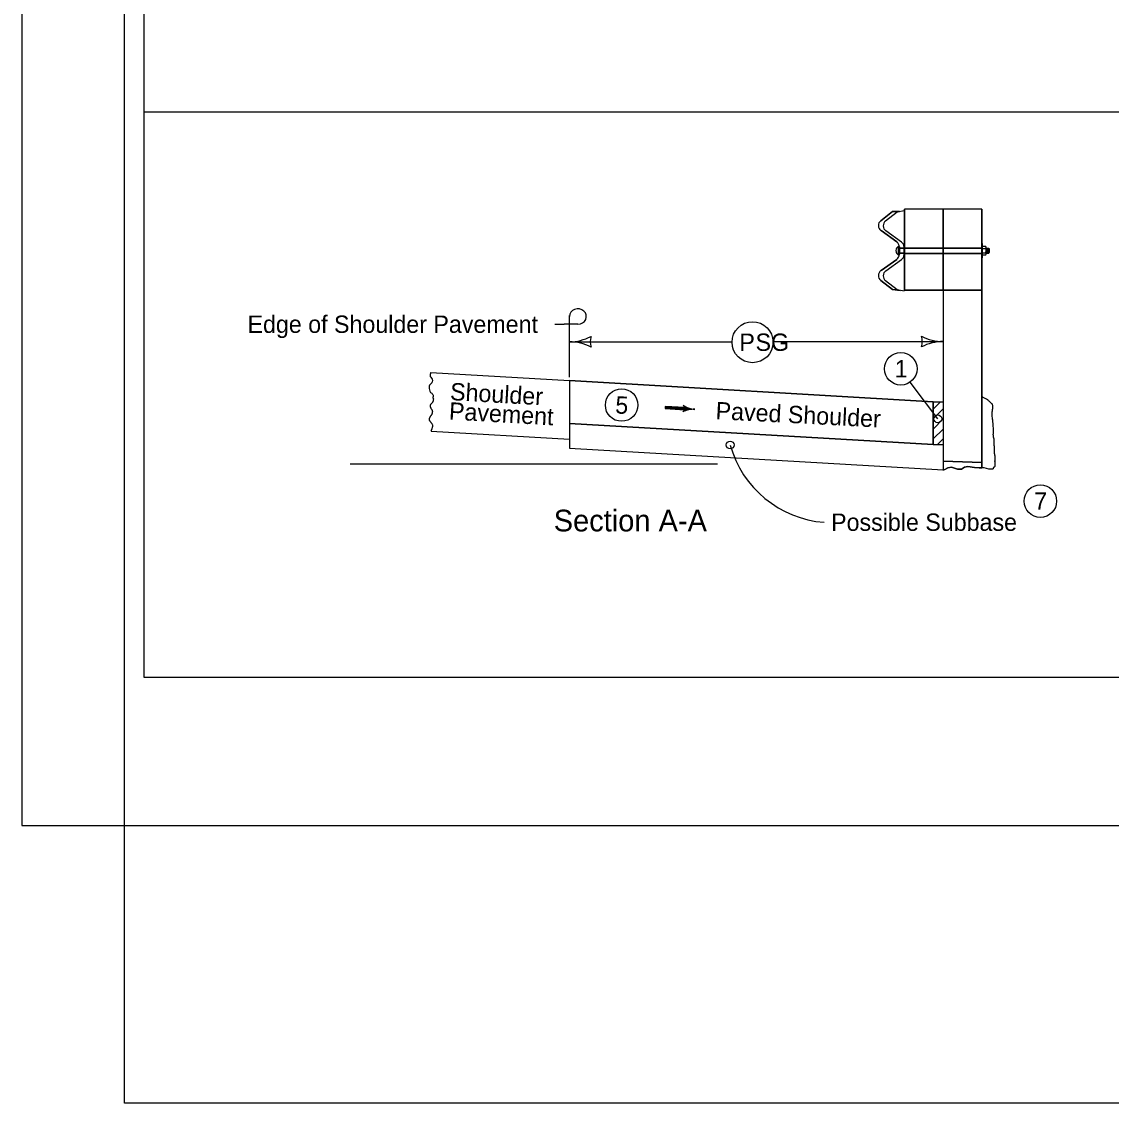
# Model space of a CAD drawing. Extents: x 10038 to 81668, y 7924 to 11018.
# Drawn here: x 10038 to 11041, y 7924 to 8921 of the extents above; entities that cross this region are included whole.
import ezdxf

# ---------------------------------------------------------------- set-up
doc = ezdxf.new("R2010")
doc.units = 0
for name, color, linetype in [('dsnCellElements', 7, 'Continuous'), ('DsnShtMinorGrid05', 7, 'Continuous'), ('DsnShtMinorGrid06', 7, 'Continuous'), ('DsnShtMinorGrid07', 7, 'Continuous'), ('DsnShtMinorGrid09', 7, 'Continuous'), ('DsnShtMinorGrid10', 7, 'Continuous'), ('DsnShtMinorGrid11', 7, 'Continuous'), ('DsnShtMinorGrid14', 7, 'Continuous'), ('Level 60', 7, 'Continuous'), ('SheetBorder', 7, 'Continuous')]:
    doc.layers.add(name, color=color, linetype=linetype)

msp = doc.modelspace()

# ---------------------------------------------------------------- linework, layer by layer
at = {"layer": 'dsnCellElements'}
msp.add_lwpolyline([(10037.7, 8180), (13358.6, 8180), (13358.6, 10373.4), (10037.7, 10373.4)], close=True, dxfattribs=at)
at = {"layer": 'DsnShtMinorGrid05'}
for p, q in [((10542.3, 8625.9), (10692.1, 8625.9)), ((10729.9, 8626.1), (10886.7, 8626.1))]:
    msp.add_line(p, q, dxfattribs=at)
msp.add_circle((10711, 8625.5), 18.9, dxfattribs=at)
for centre, radius, start, end in [((10542.3, 8668.4), 42.5, 270, 298.0725), ((10542.3, 8583.4), 42.5, 61.9275, 90), ((10577.9, 8625.9), 16.4, 162.2666, 197.7334), ((10851, 8626.1), 16.4, 342.2666, 17.7333), ((10886.7, 8668.6), 42.5, 241.9275, 270), ((10886.7, 8583.6), 42.5, 90, 118.0725), ((10784.6, 8557), 97.8, 195.5978, 265.558)]:
    msp.add_arc(centre, radius, start, end, dxfattribs=at)
at = {"layer": 'DsnShtMinorGrid06'}
for p, q in [((10150.3, 9926.7), (10150.3, 8316.7)), ((10150.3, 8316.7), (13246, 8316.7))]:
    msp.add_line(p, q, dxfattribs=at)
at = {"layer": 'DsnShtMinorGrid07'}
for p, q in [((10829.4, 8728.4), (10843.9, 8718)), ((10843.9, 8701.9), (10829.4, 8691.5))]:
    msp.add_line(p, q, dxfattribs=at)
for points in [[(10833.6, 8737.3), (10833.6, 8737.3), (10844.4, 8745.7), (10846.3, 8746), (10839.9, 8745.9), (10829.2, 8737.5)], [(10886.7, 8712.6), (10886.7, 8748.3), (10851.1, 8748.3), (10851.1, 8712.6), (10851.1, 8712.6), (10886.7, 8712.6)], [(10922.2, 8712.6), (10922.2, 8716.6), (10922.2, 8748.3), (10886.7, 8748.3), (10886.7, 8712.6), (10922.2, 8712.6)], [(10848.3, 8717.8), (10848.3, 8717.8), (10833.8, 8728.2), (10833.8, 8728.2)], [(10846.3, 8713.4), (10846.3, 8712.3), (10850.7, 8712.3), (10850.7, 8713.2), (10850.7, 8713.2)], [(10850.7, 8706.3), (10850.7, 8706.3), (10850.7, 8707.6), (10846.3, 8707.6), (10846.3, 8706.6), (10846.3, 8707.6), (10846.3, 8707.6), (10846.3, 8706.6)], [(10851.1, 8712.3), (10851.1, 8707.6), (10851.1, 8707.6), (10886.7, 8707.6), (10886.7, 8712.3), (10851.1, 8712.3), (10851.1, 8712.3)], [(10851.1, 8707.3), (10851.1, 8673.6), (10886.7, 8673.6), (10886.7, 8707.3), (10851.1, 8707.3)], [(10922.2, 8707.6), (10922.2, 8712.3), (10886.7, 8712.3), (10886.7, 8707.6), (10922.2, 8707.6)], [(10922.2, 8673.6), (10922.2, 8703.3), (10922.2, 8707.3), (10886.7, 8707.3), (10886.7, 8673.6), (10922.2, 8673.6)], [(10833.8, 8691.3), (10833.8, 8691.3), (10848.3, 8701.7), (10848.3, 8701.7)], [(10829.2, 8682.4), (10839.9, 8674), (10847, 8673.3), (10844.4, 8673.8), (10833.6, 8682.2), (10833.6, 8682.2)], [(10922.2, 8514.7), (10922.2, 8673.6), (10886.7, 8673.6), (10886.7, 8570.7), (10886.7, 8564), (10886.7, 8564), (10886.7, 8564), (10886.7, 8554.8), (10886.7, 8554.8), (10886.7, 8554.8), (10886.7, 8545.6), (10886.7, 8545.6), (10886.7, 8545.6), (10886.7, 8538.7), (10886.7, 8515.9), (10922.2, 8514.7)], [(10922.2, 8514.7), (10886.7, 8515.9), (10886.7, 8507.8), (10888.3, 8508.1), (10891, 8509.7), (10894.3, 8510.2), (10899.9, 8508.6), (10903.7, 8508.4), (10906.3, 8510.2), (10909.4, 8510.8), (10915.6, 8510.1), (10919.9, 8509.7), (10922.2, 8509.7), (10922.2, 8514.7)]]:
    msp.add_lwpolyline(points, dxfattribs=at)
msp.add_lwpolyline([(10850.7, 8712.3), (10846.3, 8712.3), (10846.3, 8708.8), (10846.3, 8710), (10846.3, 8707.6), (10850.7, 8707.6)], close=True, dxfattribs=at)
for centre, start, end in [((10832.6, 8733), 127.75, 234.6909), ((10837.1, 8732.8), 127.75, 234.6909), ((10840.6, 8713.4), 360, 54.691), ((10845, 8713.2), 360, 54.691), ((10840.6, 8706.6), 305.309, 0), ((10845, 8706.3), 305.309, 0), ((10832.6, 8686.9), 125.3091, 232.25), ((10837.1, 8686.7), 125.3091, 232.25)]:
    msp.add_arc(centre, 5.68, start, end, dxfattribs=at)
at = {"layer": 'DsnShtMinorGrid09'}
for centre, radius in [((10847.6, 8601), 15), ((10590.4, 8567.6), 15), ((10881.7, 8554.9), 3.58), ((10976.2, 8479), 15)]:
    msp.add_circle(centre, radius, dxfattribs=at)
at = {"layer": 'DsnShtMinorGrid10'}
for p, q in [((10542.3, 8629.3), (10542.3, 8650.1)), ((10528.9, 8642.1), (10537.6, 8642.1)), ((10550.1, 8642.1), (10537.6, 8642.1)), ((10542.3, 8593.3), (10542.3, 8629.3)), ((10648.6, 8564.2), (10630.4, 8565.3)), ((10648.5, 8563.3), (10648.5, 8563.3)), ((10648.7, 8565.2), (10648.7, 8565.2))]:
    msp.add_line(p, q, dxfattribs=at)
for points in [[(10648.7, 8565.2), (10630.5, 8566.2), (10630.4, 8564.3), (10648.5, 8563.3), (10648.6, 8564.9), (10630.7, 8566), (10630.7, 8564.5), (10648.2, 8563.5), (10648.3, 8564.7), (10631, 8565.7), (10630.9, 8564.7), (10647.9, 8563.7), (10648, 8564.4), (10631.1, 8565.5), (10631.1, 8564.9), (10647.7, 8564)], [(10648.3, 8566.4), (10649, 8565.2), (10648.9, 8563.6), (10648.2, 8562.2), (10650.9, 8563.1), (10654.1, 8563.7), (10655, 8563.8), (10652.8, 8564.4), (10649.6, 8565.6), (10648.6, 8566.2), (10648.7, 8562.6), (10653.7, 8563.9), (10649, 8565.4), (10649.1, 8563), (10652.5, 8564), (10649.5, 8564.8), (10649.2, 8563.4), (10651.4, 8563.9), (10649.8, 8564.4), (10649.7, 8563.8), (10650.4, 8563.9)]]:
    msp.add_lwpolyline(points, dxfattribs=at)
for centre, major_axis, start_param, end_param in [((10550.1, 8649.2), (-7.81, 0), 1.570796, 6.283185), ((10644.9, 8564.4), (3.88, 0), 5.202895, 7.237436), ((10657.1, 8543.4), (22.2, 0), 1.537172, 2.061295), ((10659.9, 8583.8), (-22.2, 0), 0.954258, 1.478381)]:
    msp.add_ellipse(centre, major_axis=major_axis, ratio=0.913811, start_param=start_param, end_param=end_param, dxfattribs=at)
at = {"layer": 'DsnShtMinorGrid11'}
for p, q in [((12305.9, 8837.7), (10150.3, 8837.7)), ((10881.7, 8554.9), (10856.3, 8588.8))]:
    msp.add_line(p, q, dxfattribs=at)
at = {"layer": 'DsnShtMinorGrid14'}
msp.add_circle((10690.4, 8530.8), 3.54, dxfattribs=at)
at = {"layer": 'Level 60'}
for p, q in [((10829.2, 8737.5), (10839.9, 8745.9)), ((10833.6, 8737.3), (10844.4, 8745.7)), ((10839.9, 8745.9), (10846.3, 8746)), ((10844.4, 8745.7), (10850.7, 8746.8)), ((10922.2, 8748.3), (10851.1, 8748.3)), ((10851.1, 8673.6), (10851.1, 8748.3)), ((10886.7, 8673.6), (10886.7, 8748.3)), ((10922.2, 8748.3), (10922.2, 8509.7)), ((10843.9, 8718), (10829.4, 8728.4)), ((10848.3, 8717.8), (10833.8, 8728.2)), ((10845.5, 8705.9), (10845.5, 8714)), ((10846.3, 8706.6), (10846.3, 8713.4)), ((10850.7, 8709.7), (10850.7, 8713.2)), ((10922.2, 8716.6), (10922.9, 8716.6)), ((10922.9, 8703.3), (10922.9, 8716.6)), ((10922.9, 8714), (10925.8, 8714)), ((10926.2, 8706.9), (10926.2, 8713)), ((10845.5, 8712.3), (10850.9, 8712.3)), ((10845.5, 8707.6), (10851.1, 8707.6)), ((10846.3, 8706.6), (10846.3, 8710)), ((10846.3, 8710), (10846.3, 8706.6)), ((10846.4, 8712.3), (10851.1, 8712.3)), ((10850.7, 8706.3), (10850.7, 8709.7)), ((10850.7, 8709.7), (10850.7, 8706.3)), ((10851.1, 8712.6), (10922.2, 8712.6)), ((10851.1, 8712.3), (10922.2, 8712.3)), ((10851.1, 8707.6), (10922.2, 8707.6)), ((10851.1, 8707.3), (10922.2, 8707.3)), ((10922.2, 8703.3), (10922.9, 8703.3)), ((10922.9, 8711.9), (10925.8, 8711.9)), ((10922.9, 8707.9), (10925.8, 8707.9)), ((10922.9, 8705.9), (10925.8, 8705.9)), ((10926.2, 8712.3), (10928.6, 8712.3)), ((10926.2, 8707.6), (10928.6, 8707.6)), ((10927.1, 8712.3), (10927.1, 8707.6)), ((10927.8, 8712.3), (10927.8, 8707.6)), ((10928.6, 8712.3), (10929, 8711.7)), ((10928.6, 8712.3), (10928.6, 8707.6)), ((10929, 8708.1), (10928.6, 8707.6)), ((10929, 8711.7), (10929, 8708.1)), ((10829.4, 8691.5), (10843.9, 8701.9)), ((10833.8, 8691.3), (10848.3, 8701.7)), ((10839.9, 8674), (10829.2, 8682.4)), ((10844.4, 8673.8), (10833.6, 8682.2)), ((10847, 8673.3), (10839.9, 8674)), ((10850.7, 8672.7), (10844.4, 8673.8)), ((10886.7, 8673.6), (10851.1, 8673.6)), ((10886.7, 8673.6), (10886.7, 8507.1)), ((10414.6, 8597.6), (10542.3, 8590.2)), ((10542.3, 8590.2), (10542.3, 8536.2)), ((10542.3, 8590.2), (10877.4, 8570.7)), ((10877.4, 8570.7), (10542.3, 8590.2)), ((10542.3, 8590.2), (10542.3, 8550.6)), ((10877.4, 8563.9), (10884.1, 8570.7)), ((10877.4, 8563.9), (10884.1, 8570.7)), ((10877.4, 8563.9), (10884.1, 8570.7)), ((10877.4, 8563.9), (10884.1, 8570.7)), ((10877.4, 8570.7), (10886.6, 8570.7)), ((10877.4, 8570.7), (10877.4, 8531.3)), ((10877.4, 8531.3), (10877.4, 8570.7)), ((10877.4, 8554.8), (10886.6, 8564)), ((10877.4, 8554.8), (10886.6, 8564)), ((10877.4, 8554.8), (10886.6, 8564)), ((10877.4, 8554.8), (10886.6, 8564)), ((10932.2, 8563.9), (10932.2, 8563.9)), ((10877.4, 8545.5), (10886.6, 8554.8)), ((10877.4, 8545.5), (10886.6, 8554.8)), ((10877.4, 8545.5), (10886.6, 8554.8)), ((10877.4, 8545.5), (10886.6, 8554.8)), ((10414.8, 8543.6), (10542.3, 8536.2)), ((10877.4, 8531.3), (10542.3, 8550.6)), ((10542.3, 8550.6), (10877.4, 8531.3)), ((10877.4, 8536.3), (10886.6, 8545.5)), ((10542.3, 8536.2), (10542.3, 8527.7)), ((10881.5, 8531.3), (10886.6, 8536.4)), ((10542.3, 8527.7), (10886.7, 8507.9)), ((10877.4, 8531.3), (10886.6, 8531.3)), ((10340.2, 8513.3), (10678.7, 8513.3))]:
    msp.add_line(p, q, dxfattribs=at)
for points in [[(10925.9, 8712), (10926, 8712), (10926.1, 8712.1), (10926.1, 8712.3), (10926.2, 8712.6), (10926.2, 8710.7), (10926.1, 8711.2), (10926.1, 8711.5), (10926, 8711.9), (10925.9, 8711.9), (10926, 8712), (10926.1, 8712.1), (10926.2, 8712.3), (10926.2, 8712.5), (10926.2, 8710.9), (10926.1, 8711.4), (10926.1, 8711.7), (10925.9, 8711.9), (10926, 8711.9), (10926.1, 8712.2), (10926.2, 8712.3), (10926.2, 8711.2), (10926, 8711.9), (10926.1, 8712.2), (10926.1, 8711.3), (10926, 8711.9), (10926.1, 8712.1), (10926.1, 8711.5), (10926, 8711.9), (10926.1, 8712.1), (10926.1, 8711.6), (10926, 8711.9), (10926.1, 8712), (10926.1, 8711.8), (10926.1, 8711.9), (10926.1, 8711.9)], [(10926.2, 8707.2), (10926.2, 8707.5), (10926.1, 8707.7), (10926, 8707.8), (10925.9, 8707.9), (10926, 8708), (10926.1, 8708.2), (10926.1, 8708.5), (10926.2, 8709.3), (10926.2, 8707.2), (10926.2, 8707.4), (10926.1, 8707.6), (10926.1, 8707.8), (10925.9, 8707.9), (10926, 8708), (10926, 8708.1), (10926.1, 8708.6), (10926.2, 8709), (10926.2, 8707.4), (10926.2, 8707.5), (10926.1, 8707.7), (10926, 8707.9), (10926, 8708.1), (10926.1, 8708.4), (10926.2, 8708.7), (10926.2, 8707.6), (10926.1, 8707.7), (10926, 8707.9), (10926, 8708.1), (10926.1, 8708.4), (10926.1, 8708.5), (10926.1, 8707.7), (10926.1, 8707.8), (10926, 8707.9), (10926.1, 8708.3), (10926.1, 8707.8), (10926, 8707.9), (10926.1, 8708.2), (10926.1, 8707.8), (10926.1, 8707.9), (10926.1, 8708), (10926.1, 8707.9)], [(10932.7, 8540.1), (10932.7, 8539.8), (10932.7, 8539.6), (10932.7, 8539.4), (10932.7, 8539.2), (10932.7, 8539), (10932.7, 8538.8), (10932.7, 8538.5), (10932.7, 8538.3), (10932.8, 8538), (10932.9, 8537.8), (10933.1, 8537.6), (10933.1, 8537.4), (10933.1, 8537.2), (10933.1, 8537), (10933.1, 8536.8), (10933.2, 8536.7), (10933.2, 8536.5), (10933.2, 8536.3), (10933.2, 8536.1), (10933.2, 8535.9), (10933.2, 8535.7), (10933.2, 8535.4), (10933.2, 8535.1), (10933.2, 8534.9), (10933.2, 8534.6), (10933.2, 8534.4), (10933.2, 8534.2), (10933.3, 8534.1), (10933.3, 8533.9), (10933.3, 8533.7), (10933.3, 8533.5), (10933.3, 8533.4), (10933.3, 8533.2), (10933.3, 8533), (10933.3, 8532.8), (10933.3, 8532.6), (10933.3, 8532.4), (10933.3, 8532.2), (10933.3, 8532), (10933.3, 8531.8), (10933.3, 8531.6), (10933.3, 8531.4), (10933.3, 8531.2), (10933.3, 8531), (10933.3, 8530.8), (10933.3, 8530.6), (10933.4, 8530.5), (10933.4, 8530.3), (10933.4, 8530.1), (10933.5, 8530), (10933.5, 8529.8), (10933.5, 8529.6), (10933.6, 8529.5), (10933.6, 8529.3), (10933.6, 8529.2), (10933.6, 8529), (10933.6, 8528.7), (10933.7, 8528.4), (10933.7, 8528.2), (10933.7, 8528), (10933.7, 8527.8), (10933.7, 8527.6), (10933.7, 8527.4), (10933.7, 8527.2), (10933.7, 8527), (10933.7, 8526.8), (10933.7, 8526.6), (10933.7, 8526.4), (10933.7, 8526.2), (10933.7, 8526), (10933.7, 8525.8), (10933.7, 8525.6), (10933.7, 8525.4), (10933.7, 8525.2), (10933.7, 8525), (10933.7, 8524.9), (10933.7, 8524.7), (10933.7, 8524.5), (10933.7, 8524.3), (10933.7, 8524.1), (10933.7, 8523.9), (10933.7, 8523.7), (10933.7, 8523.5), (10933.7, 8523.3), (10933.7, 8523.1), (10933.7, 8522.9), (10933.7, 8522.7), (10933.8, 8522.6), (10933.8, 8522.3), (10933.8, 8522.1), (10933.9, 8521.9), (10934, 8521.6), (10934, 8521.4), (10934.1, 8521.3), (10934.1, 8521.1), (10934.2, 8521), (10934.3, 8520.9), (10934.3, 8520.8), (10934.3, 8520.6), (10934.3, 8520.4), (10934.4, 8520.3), (10934.4, 8520.1), (10934.4, 8519.9), (10934.4, 8519.7), (10934.4, 8519.5), (10934.4, 8519.3), (10934.4, 8519.1), (10934.4, 8518.9), (10934.4, 8518.7), (10934.4, 8518.5), (10934.4, 8518.3), (10934.4, 8518.1), (10934.4, 8517.9), (10934.4, 8517.7), (10934.4, 8517.5), (10934.4, 8517.3), (10934.4, 8517.1), (10934.4, 8516.9), (10934.4, 8516.7), (10934.4, 8516.5), (10934.4, 8516.4), (10934.4, 8516.2), (10934.4, 8516), (10934.4, 8515.8), (10934.4, 8515.6), (10934.4, 8515.4), (10934.4, 8515.4), (10934.4, 8515.7), (10934.4, 8515.9), (10934.4, 8516.1), (10934.4, 8515.9), (10934.4, 8515.7), (10934.4, 8515.5), (10934.4, 8515.3), (10934.4, 8515.1), (10934.4, 8514.9), (10934.4, 8514.7), (10934.4, 8514.5), (10934.4, 8514.3), (10934.4, 8514.1), (10934.4, 8513.9), (10934.4, 8513.7), (10934.4, 8513.5), (10934.4, 8513.3), (10934.4, 8513.1), (10934.3, 8513), (10934.3, 8512.8), (10934.3, 8512.6), (10934.3, 8512.4), (10934.3, 8512.2), (10934.3, 8512.1), (10934.3, 8511.9), (10934.3, 8511.7), (10934.3, 8511.5), (10934.3, 8511.3), (10934.3, 8511.1), (10934.2, 8511), (10934.1, 8510.8), (10934, 8510.7), (10933.9, 8510.6), (10933.8, 8510.5), (10933.6, 8510.4), (10933.4, 8510.4), (10933.3, 8510.3), (10933.2, 8510.2), (10933.1, 8510.1), (10933, 8510), (10932.9, 8509.9), (10932.9, 8509.7), (10932.8, 8509.6), (10932.8, 8509.4), (10932.8, 8509.2), (10932.8, 8509), (10932.8, 8508.8), (10932.8, 8508.7), (10932.8, 8508.9)], [(10932.7, 8508.6), (10928.6, 8508.5), (10924.4, 8509.7), (10919.9, 8509.7), (10915.6, 8510.1), (10909.4, 8510.8), (10906.3, 8510.2), (10903.7, 8508.4), (10899.9, 8508.6), (10894.3, 8510.2), (10891, 8509.7), (10888.3, 8508.1), (10886.7, 8507.8)]]:
    msp.add_lwpolyline(points, dxfattribs=at)
msp.add_circle((10590.4, 8567.6), 15, dxfattribs=at)
for centre, radius, start, end in [((10832.6, 8733), 5.68, 127.75, 234.6909), ((10837.1, 8732.8), 5.68, 127.75, 234.6909), ((10847.6, 8709.9), 4.54, 117.2029, 242.8461), ((10840.6, 8713.4), 5.68, 360, 54.691), ((10845, 8713.2), 5.68, 360, 54.691), ((10840.6, 8706.6), 5.68, 305.309, 0), ((10845, 8706.3), 5.68, 305.309, 0), ((10832.6, 8686.9), 5.68, 125.3091, 232.25), ((10837.1, 8686.7), 5.68, 125.3091, 232.25)]:
    msp.add_arc(centre, radius, start, end, dxfattribs=at)
for centre in [(10925.8, 8713), (10925.8, 8706.9)]:
    msp.add_ellipse(centre, major_axis=(0, -1.01), ratio=0.362258, start_param=6.283156, end_param=9.424748, dxfattribs=at)
for points in [[(10414.6, 8597.6), (10414.1, 8594), (10415.2, 8592.5), (10416, 8590.2), (10415.4, 8588.1), (10413.5, 8585.8), (10413, 8583.9), (10413.5, 8581.6), (10414.4, 8579.2), (10415.4, 8578.5), (10416.8, 8575.9), (10416.8, 8575.1)], [(10414.9, 8558), (10415.1, 8558.2), (10415.3, 8558.5), (10415.6, 8559), (10415.9, 8559.6), (10416, 8559.9), (10416.1, 8560.3), (10416.2, 8560.9), (10416.3, 8561.5), (10416.2, 8562.1), (10416.2, 8562.4), (10416.2, 8562.5), (10416.1, 8562.6), (10415.9, 8563), (10415.6, 8563.4), (10415.3, 8563.7), (10415.1, 8564.1), (10414.9, 8564.4), (10414.8, 8564.7), (10414.5, 8565.3), (10414.3, 8565.8), (10414.3, 8566.1), (10414.2, 8566.4), (10414.2, 8566.6), (10414.2, 8566.7), (10414.3, 8567.5), (10414.5, 8568), (10414.8, 8568.5), (10415.3, 8569.1), (10415.8, 8569.7), (10416.3, 8570.2), (10416.5, 8570.5), (10416.7, 8570.9), (10416.9, 8571.3), (10417.1, 8571.8), (10417.2, 8572.3), (10417.2, 8572.5), (10417.2, 8572.6), (10417.2, 8572.8), (10417.2, 8573.3), (10417, 8573.8), (10417, 8573.9), (10416.9, 8574), (10416.9, 8574.2), (10416.9, 8574.3), (10416.8, 8575.1)], [(10932.7, 8540.1), (10933, 8543), (10932.8, 8547.8), (10932.4, 8553.6), (10931.7, 8558), (10931.9, 8561.3), (10932.4, 8565.5), (10931.7, 8568.6), (10929.5, 8570.6), (10927.5, 8572.4), (10925.3, 8573.5), (10923.1, 8574.8), (10922.2, 8575.5)], [(10414.9, 8558), (10414.6, 8557.7), (10414.4, 8557.5), (10414.2, 8557.3), (10414, 8557), (10413.8, 8556.7), (10413.7, 8556.4), (10413.4, 8555.9), (10413.3, 8555.6), (10413.2, 8555.3), (10413.2, 8555), (10413.1, 8554.9), (10413.1, 8554.7), (10413.1, 8554.2), (10413.2, 8553.7), (10413.5, 8553.2), (10413.7, 8552.6), (10414.2, 8552), (10414.7, 8551.5), (10415.2, 8550.9), (10415.4, 8550.6), (10415.6, 8550.3), (10416, 8549.3), (10416.1, 8548.8), (10416.1, 8548.4), (10416.1, 8548.1), (10416.1, 8547.8), (10416, 8547.5), (10415.9, 8547.2), (10415.6, 8546.1), (10415.4, 8545.5), (10415.2, 8544.9), (10415, 8544.3), (10414.9, 8544), (10414.8, 8543.7), (10414.7, 8543.6)]]:
    msp.add_spline(points, degree=3, dxfattribs=at)
at = {"layer": 'SheetBorder'}
msp.add_lwpolyline([(10132.5, 9944), (13267.5, 9944), (13267.5, 7924), (10132.5, 7924)], close=True, dxfattribs=at)

# ---------------------------------------------------------------- texts
at = {"layer": 'DsnShtMinorGrid05'}
for s, p in [('P', (10698.9, 8617.5)), ('SG', (10713.8, 8617.5))]:
    msp.add_text(s, height=16, dxfattribs=at).set_placement(p)
at = {"layer": 'DsnShtMinorGrid09'}
for s, p in [('1', (10842, 8593)), ('7', (10970.5, 8471))]:
    msp.add_text(s, height=16, dxfattribs=at).set_placement(p)
msp.add_text('5', height=16, rotation=356.6997, dxfattribs=at).set_placement((10584.2, 8559.9))
at = {"layer": 'DsnShtMinorGrid10'}
for s, height, p in [('Edge of Shoulder Pavement', 16, (10245.7, 8634.1)), ('Section A-A', 20, (10527.8, 8451.1)), ('Possible Subbase', 16, (10783.4, 8451.6))]:
    msp.add_text(s, height=height, dxfattribs=at).set_placement(p)
for s, rotation, p in [('Shoulder', 356.7346, (10432, 8572.2)), ('Pavement', 356.7346, (10431, 8554.3)), ('Paved Shoulder ', 357.0678, (10676.7, 8554.6))]:
    msp.add_text(s, height=16, rotation=rotation, dxfattribs=at).set_placement(p)

doc.saveas('drawing.dxf')
